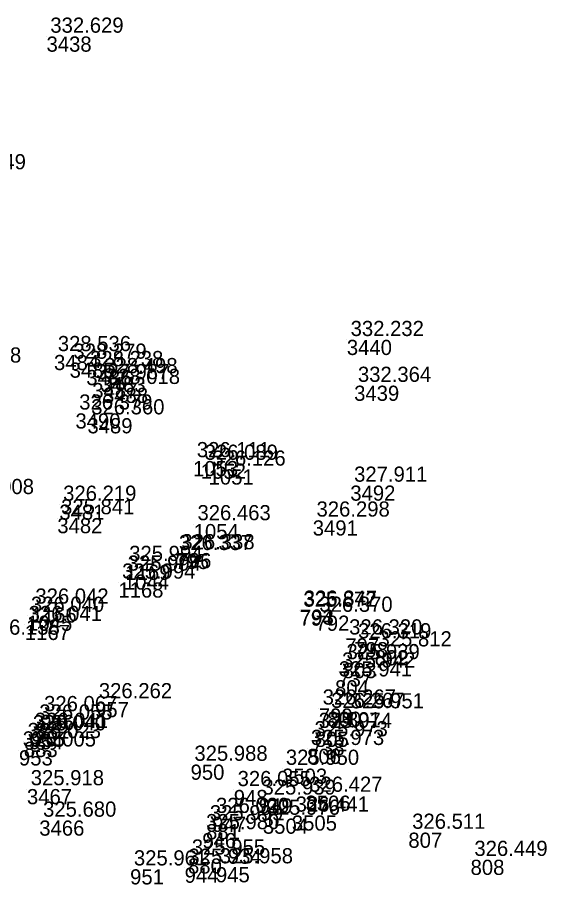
# Model space of a CAD drawing. Extents: x -829398 to -819400, y -1074439 to -1067977.
# Drawn here: x -823497.4 to -823455.5, y -1070287.3 to -1070218.7 of the extents above; entities that cross this region are included whole.
import ezdxf

# ---------------------------------------------------------------- set-up
doc = ezdxf.new("R2010")
doc.units = 0
doc.layers.add('Vrstva 60', color=7, linetype='Continuous')
doc.layers.add('Vrstva 61', color=7, linetype='Continuous')

msp = doc.modelspace()

# ---------------------------------------------------------------- linework, layer by layer
at = {"layer": 'Vrstva 60'}
for p, q in [((-823495.113, -1070220.263), (-823495.113, -1070220.263)), ((-823471.336, -1070244.252), (-823471.336, -1070244.252)), ((-823494.522, -1070245.446), (-823494.522, -1070245.446)), ((-823493.284, -1070246.048), (-823493.284, -1070246.048)), ((-823491.966, -1070246.635), (-823491.966, -1070246.635)), ((-823490.839, -1070247.19), (-823490.839, -1070247.19)), ((-823491.491, -1070247.666), (-823491.491, -1070247.666)), ((-823490.643, -1070248.042), (-823490.643, -1070248.042)), ((-823470.76, -1070247.877), (-823470.76, -1070247.877)), ((-823492.826, -1070250.068), (-823492.826, -1070250.068)), ((-823491.876, -1070250.448), (-823491.876, -1070250.448)), ((-823483.517, -1070253.836), (-823483.517, -1070253.836)), ((-823482.897, -1070254.041), (-823482.897, -1070254.041)), ((-823482.281, -1070254.503), (-823482.281, -1070254.503)), ((-823471.062, -1070255.775), (-823471.062, -1070255.775)), ((-823494.099, -1070257.284), (-823494.099, -1070257.284)), ((-823494.26, -1070258.347), (-823494.26, -1070258.347)), ((-823483.463, -1070258.821), (-823483.463, -1070258.821)), ((-823474.037, -1070258.532), (-823474.037, -1070258.532)), ((-823484.739, -1070261.115), (-823484.739, -1070261.115)), ((-823484.928, -1070261.18), (-823484.928, -1070261.18)), ((-823488.869, -1070262.043), (-823488.869, -1070262.043)), ((-823488.986, -1070262.808), (-823488.986, -1070262.808)), ((-823489.426, -1070263.441), (-823489.426, -1070263.441)), ((-823496.298, -1070265.417), (-823496.298, -1070265.417)), ((-823475.081, -1070265.66), (-823475.081, -1070265.66)), ((-823475.044, -1070265.582), (-823475.044, -1070265.582)), ((-823496.649, -1070266.066), (-823496.649, -1070266.066)), ((-823473.814, -1070266.065), (-823473.814, -1070266.065)), ((-823496.828, -1070266.795), (-823496.828, -1070266.795)), ((-823471.457, -1070267.858), (-823471.457, -1070267.858)), ((-823470.745, -1070268.161), (-823470.745, -1070268.161)), ((-823469.13, -1070268.8), (-823469.13, -1070268.8)), ((-823471.665, -1070269.811), (-823471.665, -1070269.811)), ((-823472.01, -1070270.475), (-823472.01, -1070270.475)), ((-823472.269, -1070271.175), (-823472.269, -1070271.175)), ((-823491.272, -1070272.9), (-823491.272, -1070272.9)), ((-823473.55, -1070273.402), (-823473.55, -1070273.402)), ((-823495.608, -1070273.921), (-823495.608, -1070273.921)), ((-823472.88, -1070273.661), (-823472.88, -1070273.661)), ((-823471.33, -1070273.7), (-823471.33, -1070273.7)), ((-823495.984, -1070274.586), (-823495.984, -1070274.586)), ((-823496.495, -1070275.441), (-823496.495, -1070275.441)), ((-823496.348, -1070275.244), (-823496.348, -1070275.244)), ((-823473.864, -1070275.248), (-823473.864, -1070275.248)), ((-823496.907, -1070276.051), (-823496.907, -1070276.051)), ((-823474.194, -1070275.91), (-823474.194, -1070275.91)), ((-823497.296, -1070276.719), (-823497.296, -1070276.719)), ((-823474.48, -1070276.598), (-823474.48, -1070276.598)), ((-823483.708, -1070277.849), (-823483.708, -1070277.849)), ((-823476.465, -1070278.167), (-823476.465, -1070278.167)), ((-823496.663, -1070279.782), (-823496.663, -1070279.782)), ((-823480.286, -1070279.852), (-823480.286, -1070279.852)), ((-823474.613, -1070280.301), (-823474.613, -1070280.301)), ((-823478.314, -1070280.521), (-823478.314, -1070280.521)), ((-823495.687, -1070282.269), (-823495.687, -1070282.269)), ((-823481.995, -1070281.973), (-823481.995, -1070281.973)), ((-823477.985, -1070282.116), (-823477.985, -1070282.116)), ((-823475.69, -1070281.871), (-823475.69, -1070281.871)), ((-823482.482, -1070282.557), (-823482.482, -1070282.557)), ((-823482.782, -1070283.259), (-823482.782, -1070283.259)), ((-823466.465, -1070283.228), (-823466.465, -1070283.228)), ((-823483.909, -1070285.265), (-823483.909, -1070285.265)), ((-823461.54, -1070285.374), (-823461.54, -1070285.374)), ((-823488.495, -1070286.127), (-823488.495, -1070286.127)), ((-823484.181, -1070285.995), (-823484.181, -1070285.995)), ((-823481.7, -1070285.958), (-823481.7, -1070285.958))]:
    msp.add_line(p, q, dxfattribs=at)

# ---------------------------------------------------------------- texts
for s, p in [('3438', (-823495.113, -1070221.463)), ('3440', (-823471.336, -1070245.452)), ('3484', (-823494.522, -1070246.646)), ('3485', (-823493.284, -1070247.248)), ('3486', (-823491.966, -1070247.835)), ('3483', (-823490.839, -1070248.39)), ('3487', (-823491.491, -1070248.866)), ('3488', (-823490.643, -1070249.242)), ('3439', (-823470.76, -1070249.077)), ('3490', (-823492.826, -1070251.268)), ('3489', (-823491.876, -1070251.648)), ('1053', (-823483.517, -1070255.036)), ('1052', (-823482.897, -1070255.241)), ('1051', (-823482.281, -1070255.703)), ('3492', (-823471.062, -1070256.975)), ('3481', (-823494.099, -1070258.484)), ('3482', (-823494.26, -1070259.547)), ('1054', (-823483.463, -1070260.021)), ('3491', (-823474.037, -1070259.732)), ('796', (-823484.739, -1070262.315)), ('795', (-823484.928, -1070262.38)), ('1169', (-823488.869, -1070263.243)), ('1044', (-823488.986, -1070264.008)), ('1168', (-823489.426, -1070264.641)), ('1166', (-823496.298, -1070266.617)), ('794', (-823475.081, -1070266.86)), ('793', (-823475.044, -1070266.782)), ('1045', (-823496.649, -1070267.266)), ('792', (-823473.814, -1070267.265)), ('1167', (-823496.828, -1070267.995)), ('797', (-823471.457, -1070269.058)), ('798', (-823470.745, -1070269.361)), ('802', (-823469.13, -1070270)), ('803', (-823471.665, -1070271.011)), ('737', (-823472.01, -1070271.675)), ('804', (-823472.269, -1070272.375)), ('957', (-823491.272, -1070274.1)), ('799', (-823473.55, -1070274.602)), ('956', (-823495.608, -1070275.121)), ('800', (-823472.88, -1070274.861)), ('801', (-823471.33, -1070274.9)), ('882', (-823495.984, -1070275.786)), ('954', (-823496.495, -1070276.641)), ('955', (-823496.348, -1070276.444)), ('805', (-823473.864, -1070276.448)), ('883', (-823496.907, -1070277.251)), ('738', (-823474.194, -1070277.11)), ('953', (-823497.296, -1070277.919)), ('806', (-823474.48, -1070277.798)), ('950', (-823483.708, -1070279.049)), ('3503', (-823476.465, -1070279.367)), ('3467', (-823496.663, -1070280.982)), ('948', (-823480.286, -1070281.052)), ('3506', (-823474.613, -1070281.501)), ('949', (-823478.314, -1070281.721)), ('3466', (-823495.687, -1070283.469)), ('947', (-823481.995, -1070283.173)), ('3504', (-823477.985, -1070283.316)), ('3505', (-823475.69, -1070283.071)), ('881', (-823482.482, -1070283.757)), ('946', (-823482.782, -1070284.459)), ('807', (-823466.465, -1070284.428)), ('880', (-823483.909, -1070286.465)), ('808', (-823461.54, -1070286.574)), ('951', (-823488.495, -1070287.327)), ('944', (-823484.181, -1070287.195)), ('945', (-823481.7, -1070287.158))]:
    msp.add_text(s, height=1.2, dxfattribs=at).set_placement(p)
at = {"layer": 'Vrstva 61'}
for s, p in [('332.629', (-823494.813, -1070219.963)), ('332.349', (-823502.546, -1070230.763)), ('332.232', (-823471.036, -1070243.952)), ('328.536', (-823494.222, -1070245.146)), ('328.279', (-823492.984, -1070245.748)), ('326.578', (-823502.916, -1070246.051)), ('328.238', (-823491.666, -1070246.335)), ('328.498', (-823490.539, -1070246.89)), ('327.987', (-823491.191, -1070247.366)), ('328.018', (-823490.343, -1070247.742)), ('332.364', (-823470.46, -1070247.577)), ('326.379', (-823492.526, -1070249.768)), ('326.360', (-823491.576, -1070250.148)), ('326.111', (-823483.217, -1070253.536)), ('326.089', (-823482.597, -1070253.741)), ('326.126', (-823481.981, -1070254.203)), ('327.911', (-823470.762, -1070255.475)), ('326.008', (-823501.908, -1070256.453)), ('326.219', (-823493.799, -1070256.984)), ('325.841', (-823493.96, -1070258.047)), ('326.463', (-823483.163, -1070258.521)), ('326.298', (-823473.737, -1070258.232)), ('326.337', (-823484.628, -1070260.88)), ('326.338', (-823484.439, -1070260.815)), ('325.994', (-823488.569, -1070261.743)), ('325.994', (-823488.686, -1070262.508)), ('325.994', (-823489.126, -1070263.141)), ('326.042', (-823495.998, -1070265.117)), ('325.872', (-823474.781, -1070265.36)), ('326.347', (-823474.744, -1070265.282)), ('326.040', (-823496.349, -1070265.766)), ('326.370', (-823473.514, -1070265.765)), ('326.041', (-823496.528, -1070266.495)), ('326.138', (-823499.863, -1070267.574)), ('326.320', (-823471.157, -1070267.558)), ('326.319', (-823470.445, -1070267.861)), ('325.812', (-823468.83, -1070268.5)), ('325.939', (-823471.365, -1070269.511)), ('325.942', (-823471.71, -1070270.175)), ('325.941', (-823471.969, -1070270.875)), ('326.262', (-823490.972, -1070272.6)), ('326.267', (-823473.25, -1070273.102)), ('326.067', (-823495.308, -1070273.621)), ('326.267', (-823472.58, -1070273.361)), ('325.951', (-823471.03, -1070273.4)), ('326.055', (-823495.684, -1070274.286)), ('326.040', (-823496.195, -1070275.141)), ('326.041', (-823496.048, -1070274.944)), ('325.974', (-823473.564, -1070274.948)), ('326.023', (-823496.607, -1070275.751)), ('325.973', (-823473.894, -1070275.61)), ('326.005', (-823496.996, -1070276.419)), ('325.973', (-823474.18, -1070276.298)), ('325.988', (-823483.408, -1070277.549)), ('325.950', (-823476.165, -1070277.867)), ('325.918', (-823496.363, -1070279.482)), ('326.055', (-823479.986, -1070279.552)), ('326.427', (-823474.313, -1070280.001)), ('325.939', (-823478.014, -1070280.221)), ('325.680', (-823495.387, -1070281.969)), ('326.020', (-823481.695, -1070281.673)), ('325.976', (-823477.685, -1070281.816)), ('326.441', (-823475.39, -1070281.571)), ('325.999', (-823482.182, -1070282.257)), ('325.980', (-823482.482, -1070282.959)), ('326.511', (-823466.165, -1070282.928)), ('325.955', (-823483.609, -1070284.965)), ('325.958', (-823481.4, -1070285.658)), ('326.449', (-823461.24, -1070285.074)), ('325.961', (-823488.195, -1070285.827)), ('325.934', (-823483.881, -1070285.695))]:
    msp.add_text(s, height=1.2, dxfattribs=at).set_placement(p)

doc.saveas('drawing.dxf')
